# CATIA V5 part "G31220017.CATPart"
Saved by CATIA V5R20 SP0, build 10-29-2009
Part number: G31220017
Revision: 7
Definition: design
Nomenclature: G31220017
Source: made
Description: NOT SPECIFIED
Bounding box of the stored display mesh (mm): x -8 to 17, y -15.5 to 15.5, z -15.5 to 15.5
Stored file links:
  C:\Users\Raffaele\Desktop\3D X SITO CF\BOLEX\23-BUSH REF 312\G31220017.CATPart

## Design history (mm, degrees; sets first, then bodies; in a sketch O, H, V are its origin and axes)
Body1 "MANIFOLD_SOLID_BREP #3823" (main body)
  Solid1: solid without history
Body2 "MANIFOLD_SOLID_BREP #3966"
  Solid2: solid without history
Body3 "MANIFOLD_SOLID_BREP #4109"
  Solid3: solid without history
Body4 "MANIFOLD_SOLID_BREP #4252"
  Solid4: solid without history
Body5 "MANIFOLD_SOLID_BREP #4395"
  Solid5: solid without history
Body6 "MANIFOLD_SOLID_BREP #4540"
  Solid6: solid without history
Body7 "MANIFOLD_SOLID_BREP #4685"
  Solid7: solid without history
Body8 "MANIFOLD_SOLID_BREP #4830"
  Solid8: solid without history
Body9 "MANIFOLD_SOLID_BREP #4975"
  Solid9: solid without history
Body10 "MANIFOLD_SOLID_BREP #5120"
  Solid10: solid without history
Body11 "MANIFOLD_SOLID_BREP #5265"
  Solid11: solid without history
Body12 "MANIFOLD_SOLID_BREP #5410"
  Solid12: solid without history
Body13 "MANIFOLD_SOLID_BREP #5555"
  Solid13: solid without history
Body14 "MANIFOLD_SOLID_BREP #5700"
  Solid14: solid without history
Body15 "MANIFOLD_SOLID_BREP #5845"
  Solid15: solid without history
Body16 "MANIFOLD_SOLID_BREP #5990"
  Solid16: solid without history
Body17 "MANIFOLD_SOLID_BREP #6135"
  Solid17: solid without history
Body18 "MANIFOLD_SOLID_BREP #6280"
  Solid18: solid without history
Body19 "MANIFOLD_SOLID_BREP #6425"
  Solid19: solid without history
Body20 "MANIFOLD_SOLID_BREP #6570"
  Solid20: solid without history
Body21 "MANIFOLD_SOLID_BREP #6715"
  Solid21: solid without history
Body22 "MANIFOLD_SOLID_BREP #6862"
  Solid22: solid without history
Body23 "MANIFOLD_SOLID_BREP #7007"
  Solid23: solid without history
Body24 "MANIFOLD_SOLID_BREP #7152"
  Solid24: solid without history
Body25 "MANIFOLD_SOLID_BREP #7299"
  Solid25: solid without history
